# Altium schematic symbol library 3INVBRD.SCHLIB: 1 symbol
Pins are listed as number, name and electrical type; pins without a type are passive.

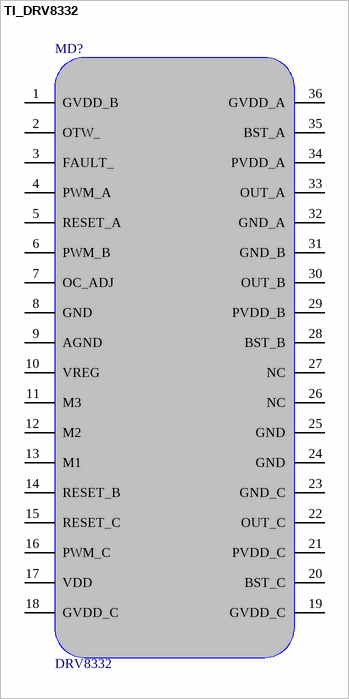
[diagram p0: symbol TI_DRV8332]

## TI_DRV8332
designator MD?, comment DRV8332
3 Phase Integrated Motor Driver by Texas Instruments
footprint HSSOP36 (TI 8332 DKD Package)
footprint SOP36n
pins: 1 GVDD_B, 2 OTW_, 3 FAULT_, 4 PWM_A, 5 RESET_A, 6 PWM_B, 7 OC_ADJ, 8 GND, 9 AGND, 10 VREG, 11 M3, 12 M2, 13 M1, 14 RESET_B, 15 RESET_C, 16 PWM_C, 17 VDD, 18 GVDD_C, 19 GVDD_C, 20 BST_C, 21 PVDD_C, 22 OUT_C, 23 GND_C, 24 GND, 25 GND, 26 NC, 27 NC, 28 BST_B, 29 PVDD_B, 30 OUT_B, 31 GND_B, 32 GND_A, 33 OUT_A, 34 PVDD_A, 35 BST_A, 36 GVDD_A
